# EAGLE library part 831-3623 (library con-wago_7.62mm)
Serie 831, Stiftleiste (für Leiterplatten) mit abgewinkelten Einlötstiften / Series 831, Male header (for PCBs) with angled solder pins Polzahl / Pole No.: 3 Bemessungsspannung / Rated Voltage: 630 V Nennstrom / Nominal Current: 41 A Lötstiftlänge: / Solder Pin Length: 4 mm Farbe / Color: lichtgrau / light gray Stand: 01.01.2012. Die jeweils aktuellen Daten zu diesem Artikel finden Sie in unserem Produktkatalog, den Sie unter www.wago.com einsehen können. As of: 01/01/2012. Please find the newest data for this article in our product catalogue, which can be viewed under www.wago.com.
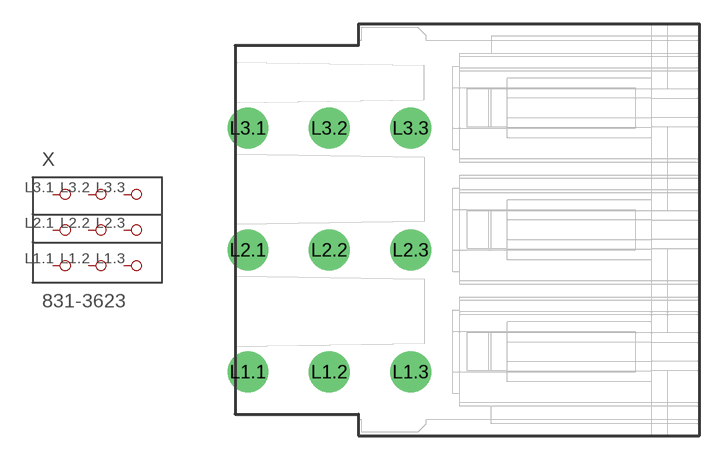
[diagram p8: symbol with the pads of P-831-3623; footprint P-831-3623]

Designator prefix X

## 831-3623  [P-831-3623]
L1.1  P1.1
L1.2  P1.2
L1.3  P1.3
L2.1  P2.1
L2.2  P2.2
L2.3  P2.3
L3.1  P3.1
L3.2  P3.2
L3.3  P3.3

## Footprint P-831-3623 (pad centres in mm)
drill 1.7 round: L1.1 -13.7,-8.87; L1.2 -8.62,-8.87; L1.3 -3.54,-8.87; L2.1 -13.7,-1.25; L2.2 -8.62,-1.25; L2.3 -3.54,-1.25; L3.1 -13.7,6.37; L3.2 -8.62,6.37; L3.3 -3.54,6.37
